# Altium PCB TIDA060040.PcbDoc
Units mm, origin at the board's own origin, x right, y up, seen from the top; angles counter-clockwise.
Board outline 50.79 x 50.79 mm, 2 copper layers (Top Layer, Bottom Layer), stack 1.575 mm thick; 49 components, 44 nets, 120 pads, 42 vias.
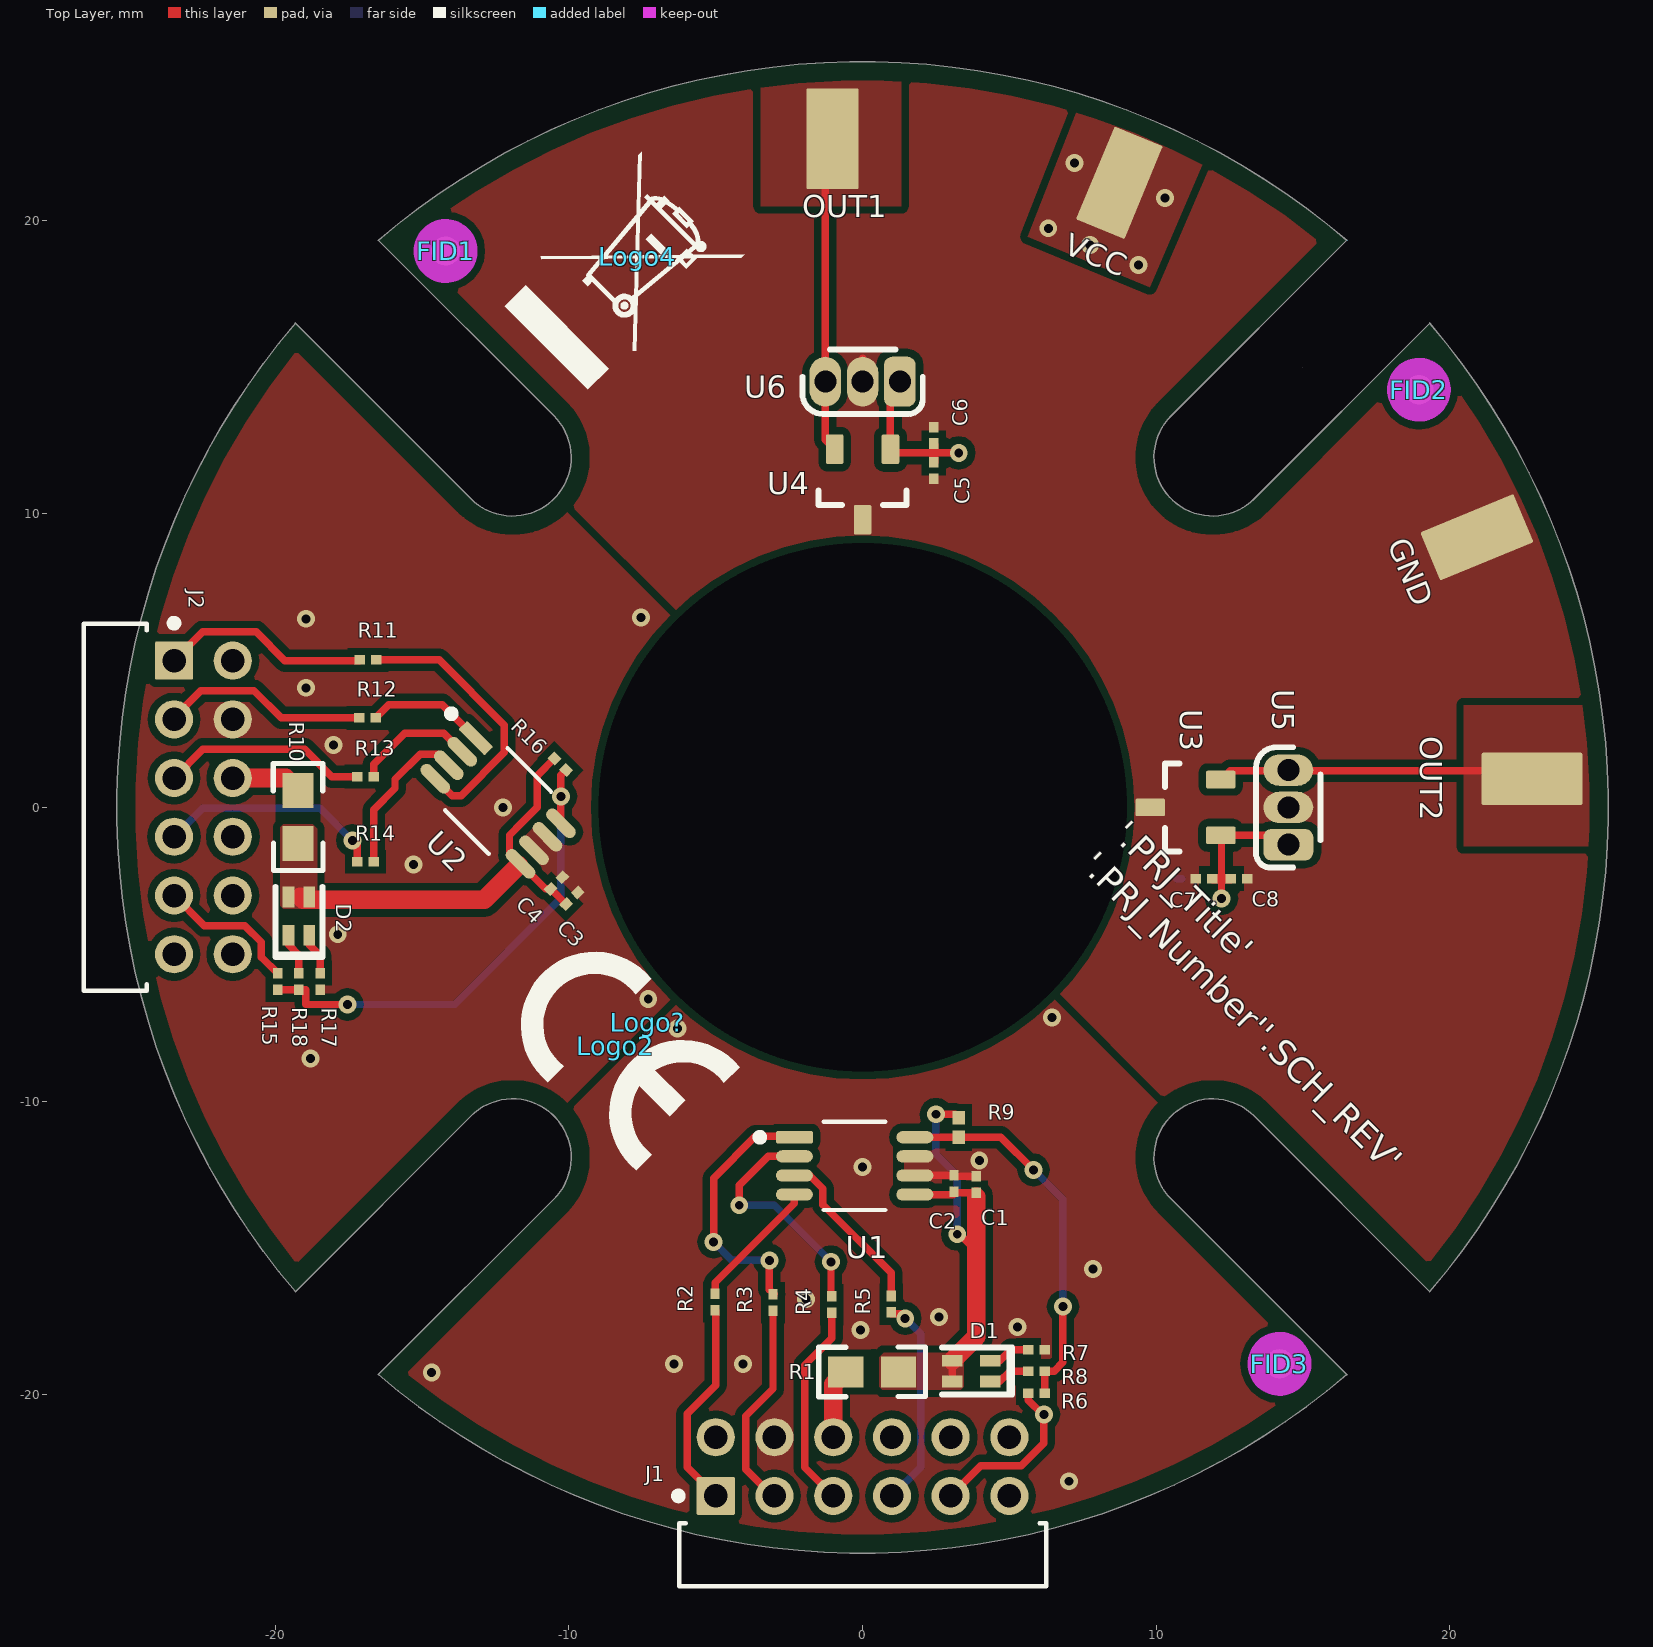
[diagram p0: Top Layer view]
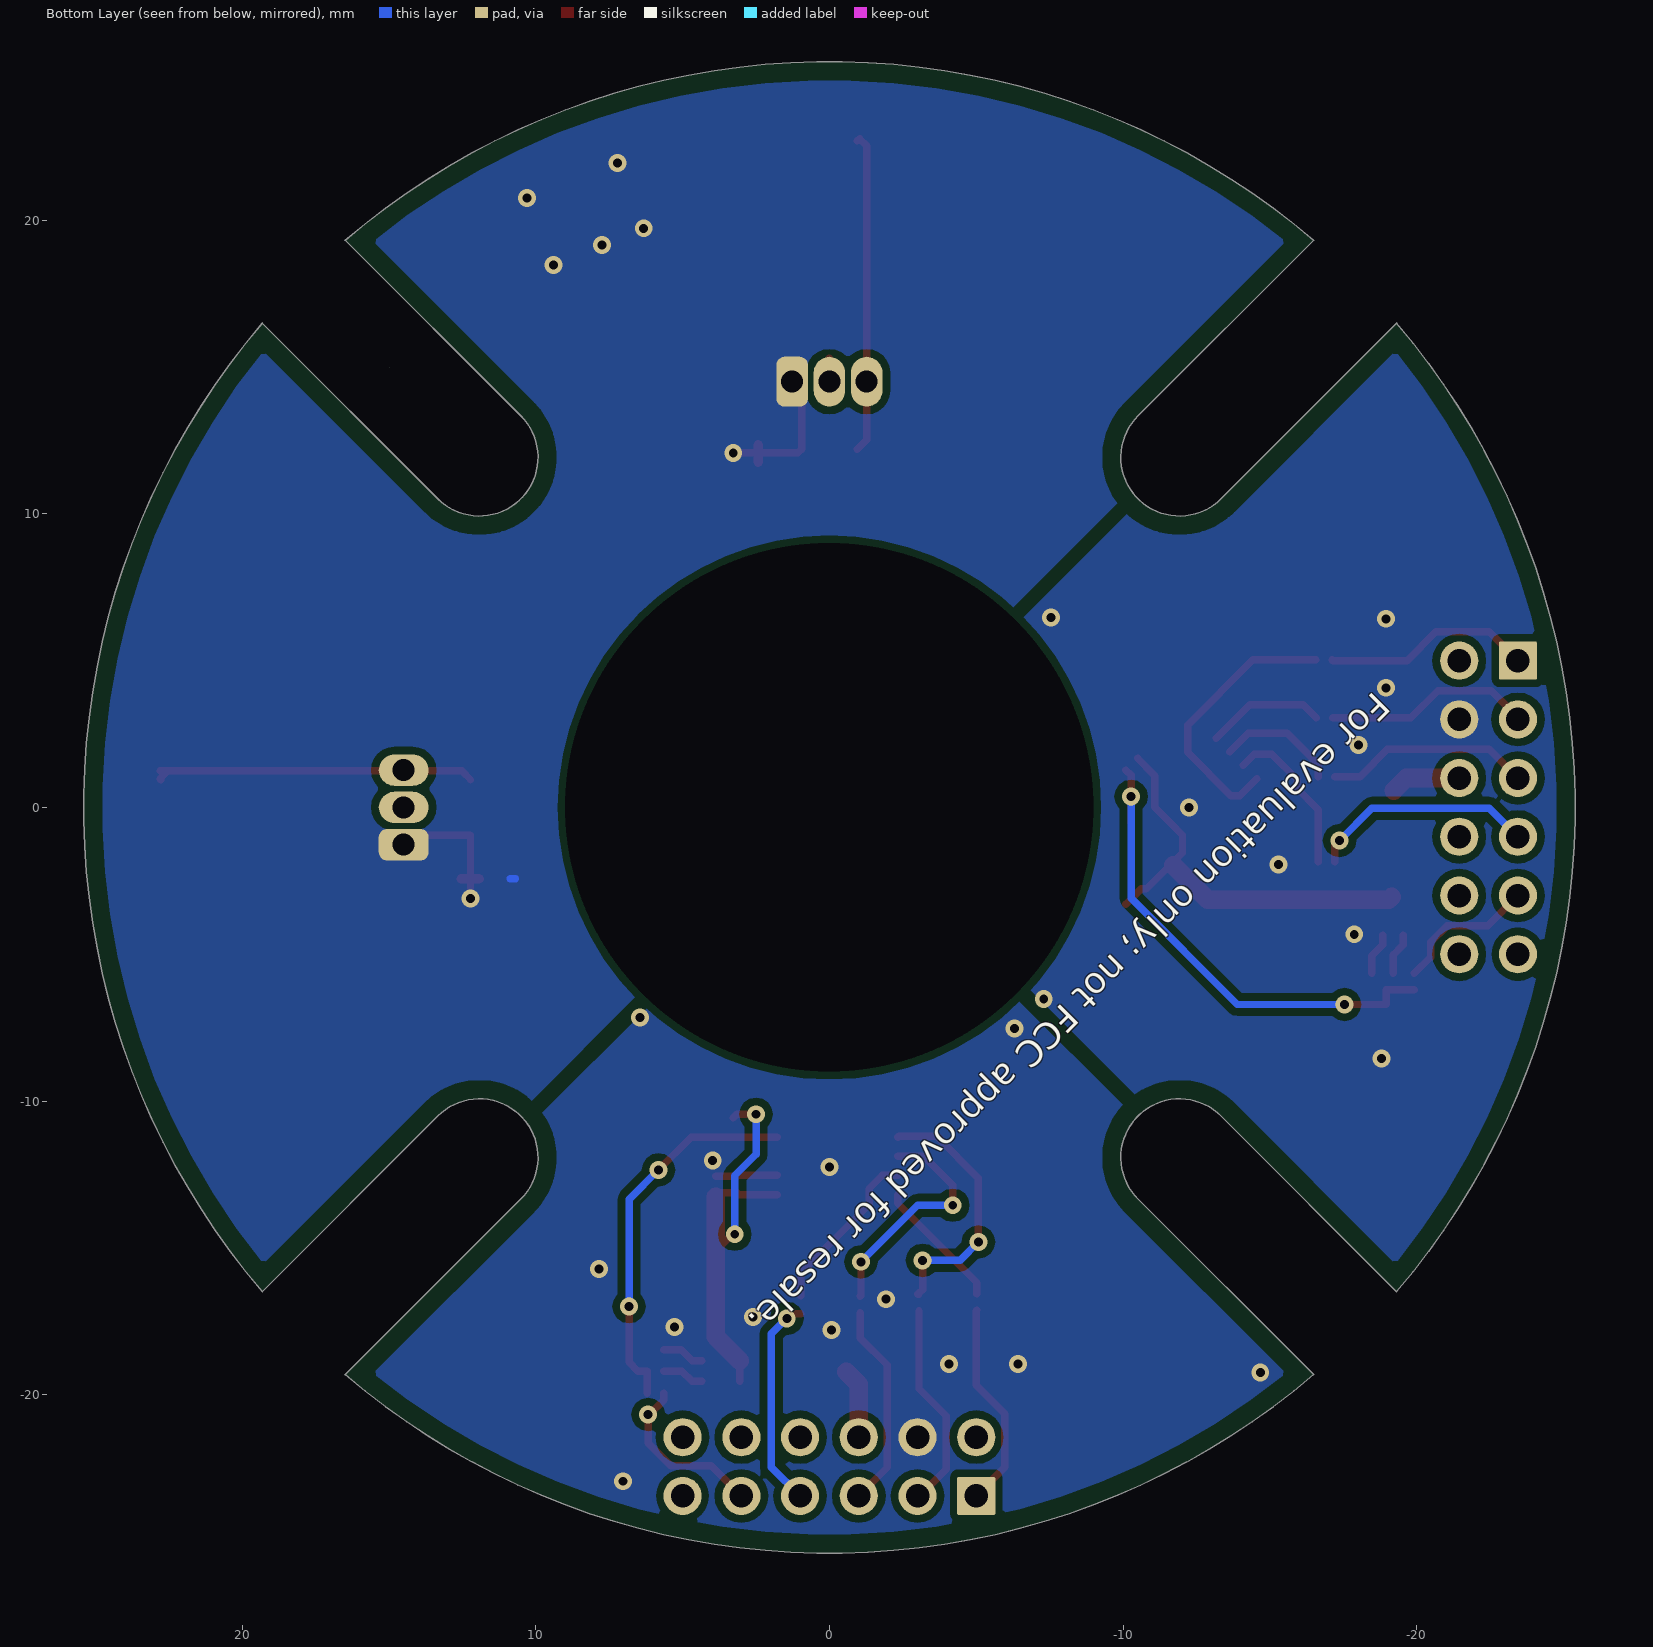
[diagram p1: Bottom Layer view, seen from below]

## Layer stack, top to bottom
Top Solder: solder mask 0.0102, Solder Resist, Dk 3.5
Top Layer: signal copper 0.0356
Dielectric1: core 1.5037, FR-4, Dk 4.8
Bottom Layer: signal copper 0.0356
Bottom Solder: solder mask 0.0102, Solder Resist, Dk 3.5

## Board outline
-19.325,-16.5 -13.339,-10.514 -13.339,-10.511 cw(c-11.925,-11.925) -10.511,-13.339 -10.514,-13.339 -16.5,-19.325 -16.493,-19.317 ccw(c0,0) 16.493,-19.317 16.5,-19.325 10.514,-13.339 10.511,-13.339 cw(c11.925,-11.925) 13.339,-10.511 13.339,-10.514 19.325,-16.5 19.317,-16.493 ccw(c0,0) 19.317,16.493 19.325,16.5 13.339,10.514 13.339,10.511 cw(c11.925,11.925) 10.511,13.339 10.514,13.339 16.5,19.325 16.493,19.317 ccw(c0,0) -16.493,19.317 -16.5,19.325 -10.514,13.339 -10.511,13.339 cw(c-11.925,11.925) -13.339,10.511 -13.339,10.514 -19.325,16.5 -19.317,16.493 ccw(c0,0)
cut-out: 16.5,19.325
cut-out: 15,15

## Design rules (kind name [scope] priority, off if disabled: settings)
AcuteAngle [All] p1: minimum=4.50000000000000E+0001 checktracksonly=FALSE
AssemblyTestPointUsage [All] p1: valid=2
BoardOutlineClearance BoardOutlineClearance_MountingHoles [OnCopper and InComponentClass('Mounting Holes')] p1: gap=1 ignorepadtopadclearanceinfootprint=FALSE
BoardOutlineClearance BoardOutlineClearance_Poly [OnCopper and IsPoly] p2: gap=0.635 ignorepadtopadclearanceinfootprint=FALSE
BoardOutlineClearance [OnCopper and Not InComponentClass('Logo') and not InComponentClass('FiducialMark') and not InRegion(1000,500,4000,800) and not InPoly] p3: gap=0.635 ignorepadtopadclearanceinfootprint=FALSE
Clearance Clearance_Keepouts [((IsTrack Or IsArc) And Not InPoly) And IsFree and IsKeepOut vs ((IsTrack Or IsArc) And Not InPoly) And IsFree and IsKeepOut] p1: gap=0 ignorepadtopadclearanceinfootprint=FALSE
Clearance Clearance_Poly [InPolygon] p2: gap=0.254 ignorepadtopadclearanceinfootprint=TRUE
Clearance Clearance_FiducialMark [IsKeepOut and InComponentClass('FiducialMark') vs IsPad and InComponentClass('FiducialMark')] p3: gap=0 ignorepadtopadclearanceinfootprint=FALSE
Clearance [All] p4: gap=0.2 ignorepadtopadclearanceinfootprint=TRUE
ComponentClearance ComponentClearance_MountingHoles_FiducialMarks [InComponentClass('Mounting Holes') vs InComponentClass('FiducialMark')] p1: gap=1.27 collisioncheckmode=3 verticalgap=0.254 showdistances=FALSE
ComponentClearance ComponentClearance_Shunt [InComponentClass('Header') vs InComponentClass('Shunt')] p2: gap=0 collisioncheckmode=3 verticalgap=0 showdistances=FALSE
ComponentClearance ComponentClearance_Logo [InComponentClass('Logo')] p3: gap=1.27 collisioncheckmode=3 verticalgap=0.254 showdistances=FALSE
ComponentClearance ComponentClearance_ScrewToNut [(HasFootprint('NY PMS 440 0025 PH')) vs (HasFootprint('Keystone_1902C'))] p4: gap=0.127 collisioncheckmode=3 verticalgap=0.254 showdistances=FALSE
ComponentClearance ComponentClearance_MountingHoles [InComponentClass('Mounting Holes')] p5: gap=6.35 collisioncheckmode=3 verticalgap=2540 showdistances=FALSE
ComponentClearance ComponentClearance_SmallPassives [HasFootprint('0201*') or HasFootprint('0402*') or HasFootprint('0508') or HasFootprint('0603*') or HasFootprint('0612') or HasFootprint('0805*') or HasFootprint('0815*') or HasFootprint('0830*') or HasFootprint('1206*') or HasFootprint('1210*') or HasFootprint('1808*') or HasFootprint('1812*') or HasFootprint('1825*') or HasFootprint('2010*') or HasFootprint('2220*') or HasFootprint('2225*') or HasFootprint('2512*') or HasFootprint('2728*') or HasFootprint('3518*') vs HasFootprint('0201*') or HasFootprint('0402*') or HasFootprint('0508') or HasFootprint('0603*') or HasFootprint('0612') or HasFootprint('0805*') or HasFootprint('0815*') or HasFootprint('0830*') or HasFootprint('1206*') or HasFootprint('1210*') or HasFootprint('1808*') or HasFootprint('1812*') or HasFootprint('1825*') or HasFootprint('2010*') or HasFootprint('2220*') or HasFootprint('2225*') or HasFootprint('2512*') or HasFootprint('2728*') or HasFootprint('3518*')] p6: gap=0.38 collisioncheckmode=3 verticalgap=0.254 showdistances=FALSE
ComponentClearance ComponentClearance_THtoSMT [IsThruComponent vs IsSMTComponent] p7: gap=1.016 collisioncheckmode=3 verticalgap=0.762 showdistances=FALSE
ComponentClearance ComponentClearance_THtoTH [IsThruComponent vs IsThruComponent] p8: gap=0.762 collisioncheckmode=3 verticalgap=0.762 showdistances=FALSE
ComponentClearance [All] p9: gap=0.762 collisioncheckmode=3 verticalgap=0.254 showdistances=FALSE
DiffPairsRouting [All] p1: maxlimit=2.54 minlimit=0.254 mostfreqgap=0.254 toplayer_minwidth=0.381 toplayer_maxwidth=0.381 toplayer_prefwidth=0.381 bottomlayer_minwidth=0.381 bottomlayer_maxwidth=0.381 bottomlayer_prefwidth=0.381 maxuncoupledlength=25.4
FabricationTestPointUsage TestPointUsage [All] p1: valid=2 allowmultiple=FALSE
FabricationTestpoint Testpoint [All] p1: side=3 testpointundercomponent=TRUE minsize=1.016 maxsize=2.54 preferedsize=1.524 minholesize=0 maxholesize=1.016 preferedholesize=0.813 testpointgrid=0.025 allowsidetop=TRUE allowsidebottom=TRUE usegrid=TRUE gridtolerance=0
FanoutControl Fanout_LCC [IsLCC] p1: bgadir=Out bgaviamode=Centered fanoutstyle=Auto fanoutdirection=Alternating viagrid=0.025 // Fanout_LCC (Default Rule)
FanoutControl Fanout_BGA [IsBGA] p2: bgadir=Out bgaviamode=Centered fanoutstyle=Auto fanoutdirection=Alternating viagrid=0.025 // Fanout_BGA (Default Rule)
FanoutControl Fanout_Default [All] p4: bgadir=Out bgaviamode=Centered fanoutstyle=Auto fanoutdirection=Alternating viagrid=0.025 // Fanout_Default (Default Rule)
FanoutControl Fanout_Small [(CompPinCount < 5)] p5: bgadir=Out bgaviamode=Centered fanoutstyle=Auto fanoutdirection=OutThenIn viagrid=0.025 // Fanout_Small (Default Rule)
HoleSize [All] p1: absolutevalues=TRUE maxlimit=25.4 minlimit=0.2 maxpercent=80.000 minpercent=20.000
MinimumAnnularRing MinimumAnnularRing_ThermalPadVias [IsVia and InAnyComponent] p1: minimumring=0.152
MinimumAnnularRing [All] p2: minimumring=0.152
MinimumSolderMaskSliver MinimumSolderMaskSliver_Logo [InComponentClass('Logo') vs InComponentClass('Logo')] p1: minsoldermaskwidth=0.018
MinimumSolderMaskSliver [All] p2: minsoldermaskwidth=0.1
PlaneConnect [All] p1: planeconnectstyle=Relief reliefexpansion=0.254 reliefentries=4 reliefconductorwidth=0.254 reliefairgap=0.254
PolygonConnect PolygonConnect_Trace [InNet('NetJ1_5') OR InNet('NetJ1_3')] p1: connectstyle=Direct reliefconductorwidth=0.254 reliefentries=4 polygonreliefangle="90 Angle" airgapwidth=0.254
PolygonConnect [All] p2: connectstyle=Direct reliefconductorwidth=0.254 reliefentries=4 polygonreliefangle="90 Angle" airgapwidth=0.254
RoutingVias ThermalPadVias [IsVia and InAnyComponent] p1: holewidth=0.2 width=0.5 viastyle="Through Hole" minholewidth=0.2 minwidth=0.5 maxholewidth=0.33 maxwidth=0.6
RoutingVias [All] p2: holewidth=0.254 width=0.559 viastyle="Through Hole" minholewidth=0.2 minwidth=0.5 maxholewidth=1.016 maxwidth=1.651
SilkToBoardRegionClearance [Not ((IsComment or IsDesignator) And (Hide <> 'False')) and not InRegion(1000,500,4000,800)] p1:
SilkToSilkClearance SilkToSilkClearance_Pb-FreeLogo [(HasFootprint('Pb-Free_Overlay_Medium') OR HasFootprint('Pb-Free_Overlay_Small')) vs (HasFootprint('Pb-Free_Overlay_Medium') OR HasFootprint('Pb-Free_Overlay_Small'))] p1: silktosilkclearance=0
SilkToSilkClearance [All] p2: silktosilkclearance=0.1
SilkToSolderMaskClearance SilkToComponentPadClearance [(IsPad or IsFill or IsRegion) and InAnycomponent] p1: minsilkscreentomaskgap=0.127 clearancetoexposedcopper=TRUE
SilkToSolderMaskClearance "Silk to Solder Mask Opening" [All] p2: minsilkscreentomaskgap=0.1 clearancetoexposedcopper=FALSE
SolderMaskExpansion [All] p1: expansion=0.05
UnRoutedNet [All] p1: checkbadconnections=TRUE
Width [All] p1: maxlimit=2.54 minlimit=0.152 preferedwidth=0.254 checkconnectedcopper=TRUE
14 further rules are at their usual default settings.

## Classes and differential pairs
component class Robotics: C1 C2 C3 C4 C5 C6 C7 C8 D1 D2 GND J1 J2 J4 J5 J? OUT1 OUT2 R1 R2 R3 R4 R5 R6 R7 R8 R9 R10 R11 R12 R13 R14 R15 R16 R17 R18 U1 U2 U3 U4 U5 U6 VCC
component class Robotics_HW: FID1 FID2 FID3 Logo2 Logo4 Logo? ZZ1 ZZ2 ZZ3
component class FiducialMark: FID1 FID2 FID3
component class AssemblyNote: ZZ1 ZZ2 ZZ3

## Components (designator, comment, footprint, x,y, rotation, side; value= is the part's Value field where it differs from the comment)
C1 "CL03A105MP3NSNC" 0201L 3.875,-12.845 r270 top value=1uF
C2 "GRM033R60J104KE19D" 0201_033L 3.115,-12.815 r90 top value=0.1uF
C3 "CL03A105MP3NSNC" 0201L -9.898,-3.098 r225 top value=1uF
C4 "GRM033R60J104KE19D" 0201_033L -10.425,-2.575 r45 top value=0.1uF
C5 "CL03A105MP3NSNC" 0201L 2.425,11.475 r90 top value=1uF
C6 "GRM033R60J104KE19D" 0201_033L 2.425,12.675 r90 top value=0.1uF
C7 "CL03A105MP3NSNC" 0201L 11.625,-2.425 r0 top value=1uF
C8 "GRM033R60J104KE19D" 0201_033L 12.824,-2.425 r0 top value=0.1uF
D1 "HSMF-C165" HSMF-C165_RG 3.7,-19.2 r0 top value=Rg
D2 "HSMF-C165" HSMF-C165_RG -19.2,-3.7 r270 top value=Rg
FID1 "Fiducial" Fiducial10-20 -14.2,18.95 r0 top
FID2 "Fiducial" Fiducial10-20 18.95,14.225 r0 top
FID3 "Fiducial" Fiducial10-20 14.2,-18.95 r0 top
GND "DRV5055 GND" Keystone_5017 20.925,9.2 r22.5 top
J1 "NRPN062PARN-RC" FP-NRPN062PARN-RC_HDR12-MFG 0,-25.45 r0 top
J2 "NRPN062PARN-RC" FP-NRPN062PARN-RC_HDR12-MFG -25.45,0 r270 top
Logo2 "CE Mark" CE_Mark_5mm -8.425,-8.125 r315 top
Logo4 "WEEE logo" WEEE_Minimum -7.675,18.75 r315 top
Logo? "FCC disclaimer" FCC_disclaimer -7.325,-7.325 r315 top
OUT1 "DRV5055 OUT2" Keystone_5017 -1.025,22.775 r90 top
OUT2 "DRV5055 OUT1" Keystone_5017 22.8,0.975 r180 top
R1 "CRCW06030000Z0EA" 0603M 0.325,-19.225 r180 top value=0
R2 "CRCW02010000Z0ED" 0201L -5.025,-16.845 r90 top value=0
R3 "CRCW02010000Z0ED" 0201L -3.05,-16.865 r90 top value=0
R4 "CRCW02010000Z0ED" 0201L -1.05,-16.935 r90 top value=0
R5 "CRCW02010000Z0ED" 0201L 0.975,-16.92 r90 top value=0
R6 "CRCW02010000Z0ED" 0201L 5.925,-19.95 r0 top value=0
R7 "RC0201JR-07150RL" 0201L 5.925,-18.475 r0 top value=150
R8 "RC0201JR-07150RL" 0201L 5.925,-19.2 r0 top value=150
R9 "RC0201JR-7D4K7L" 0201 3.275,-10.9 r90 top value=4.7k
R10 "CRCW06030000Z0EA" 0603M -19.225,-0.325 r90 top value=0
R11 "CRCW02010000Z0ED" 0201L -16.845,5.025 r0 top value=0
R12 "CRCW02010000Z0ED" 0201L -16.865,3.05 r0 top value=0
R13 "CRCW02010000Z0ED" 0201L -16.935,1.05 r0 top value=0
R14 "CRCW02010000Z0ED" 0201L -16.93,-1.85 r0 top value=0
R15 "CRCW02010000Z0ED" 0201L -19.925,-5.925 r270 top value=0
R16 "CRCW02010000Z0ED" 0201L -10.296,1.471 r135 top value=4.7k
R17 "RC0201JR-07150RL" 0201L -18.475,-5.925 r270 top value=150
R18 "RC0201JR-07150RL" 0201L -19.2,-5.925 r270 top value=150
U1 "PTMAG5170A1EDGKQ1" DGK0008A-IPC_C -0.27,-12.21 r0 top
U2 "PTMAG5170A1EDGKQ1" DGK0008A-IPC_C -12.413,0.219 r315 top locked
U3 "DRV5055A1QDBZT" DBZ0003A_N 11,0 r180 top
U4 "DRV5055A1QDBZT" DBZ0003A_N 0,11 r270 top
U5 "DRV5055A1QLPGM" LPG0003A 14.5,0 r90 top
U6 "DRV5055A1QLPGM" LPG0003A 0,14.5 r180 top
VCC "DRV5055 VCC" Keystone_5017 8.75,21.275 r247.5 top
ZZ1 "These assemblies are ESD sensitive, ESD precautions shall be observed." AssemblyNote -61.119,49.567 r0 top
ZZ2 "These assemblies must be clean and free from flux and all contaminants. Use of no clean flux is not acceptable." AssemblyNote -61.119,47.318 r0 top
ZZ3 "These assemblies must comply with workmanship standards IPC-A-610 Class 2, unless otherwise specified." AssemblyNote -61.119,45.068 r0 top

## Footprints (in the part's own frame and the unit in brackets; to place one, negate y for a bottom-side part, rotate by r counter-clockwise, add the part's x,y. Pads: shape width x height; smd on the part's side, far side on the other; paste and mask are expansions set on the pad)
0201 [mm] "Data from Kemet datasheet CC101_COM dated 7/28/11"
  rect 0.46x0.42 smd mask+0.048: 1(-0.33,0) 2(0.33,0)
  body extent -0.31,-0.16 0.31,0.16, height 0.26
0201_033L [mm] "0201"
  rect 0.36x0.32 smd mask+0.048: 1(-0.28,0) 2(0.28,0)
  body extent -0.31,-0.16 0.31,0.16, height 0.33
0201L [mm] "Data from Kemet datasheet CC101_COM dated 7/28/11"
  rect 0.36x0.32 smd mask+0.048: 1(-0.28,0) 2(0.28,0)
  body extent -0.31,-0.16 0.31,0.16, height 0.26
0603M [mm] "0603 from SM-752 data"
  rect 1.2x1.05 smd: 1(-0.9,0) 2(0.9,0)
  silkscreen extent -1.82,-0.84 1.82,0.84, body extent -0.87,-0.47 0.87,0.47, height 1
AssemblyNote [mm] "Assembly Note"
CE_Mark_5mm [mm] "Minimum text height for CE Mark"
  silkscreen extent -3.5,-2.5 3.5,2.5
DBZ0003A_N [mm] "SOT23, 3-Leads, Body 2.9x1.3mm, Pitch 0.95mm, Lead Span 2.4mm, IPC Medium Density"
  rrect17% 1x0.6 smd: 1(-1.2,0.95) 2(-1.2,-0.95) 3(1.2,0)
  silkscreen extent 0.2,-1.5 0.7,1.5, body extent -1.26,-1.46 1.26,1.46, height 0.98
DGK0008A-IPC_C [mm]
  rrect24% 1.257x0.418 smd paste+0 mask+0: 1(-2.051,0.975)
  rrect100% 1.257x0.418 smd paste+0 mask+0: 2(-2.051,0.325) 3(-2.051,-0.325) 4(-2.051,-0.975) 5(2.051,-0.975) 6(2.051,-0.325) 7(2.051,0.325) 8(2.051,0.975)
  silkscreen extent -3.35,-1.5 1.05,1.5, body extent -2.78,-1.6 2.78,1.6, height 0.25
FCC_disclaimer [mm]
Fiducial10-20 [mm]
  round 1 smd mask+0.5: 1(0,0)
  Top Layer keep-out circle w1.178: c0,0 r0.5
FP-NRPN062PARN-RC_HDR12-MFG [mm]
  rrect8% 1.3x1.3 hole 0.8 paste-1000 mask+0: 1(-5,2)
  round 1.3 hole 0.8 paste-1000 mask+0: 2(-5,4) 3(-3,2) 4(-3,4) 5(-1,2) 6(-1,4) 7(1,2) 8(1,4) 9(3,2) 10(3,4) 11(5,2) 12(5,4)
  silkscreen extent -6.4,-1.07 6.25,2.12, body extent -6.35,-5.02 6.35,4.75, height 0.25
HSMF-C165_RG [mm] "SMD, 4-Leads, Body 1.6x0.8mm"
  rect 0.7x0.4 smd: 1(-0.65,0.35) 2(-0.65,-0.35) 3(0.65,0.35) 4(0.65,-0.35)
  silkscreen extent -1,-0.8 1.5,0.8, body extent -0.85,-0.45 0.85,0.45, height 0.51
Keystone_5017 [mm] "PC Test Point, SMT"
  rrect6% 3.43x1.78 smd: 1(0,0)
  body extent -1.35,-0.51 1.35,0.51, height 1.51
LPG0003A [mm] "TO, Flat Index; 3 In-Line, Axial Leads Texas Instruments Recommended"
  rrect50% 1.07x1.7 hole 0.75: 1(-1.27,0)
  oval 1.07x1.7 hole 0.75: 2(0,0) 3(1.27,0)
  silkscreen extent -2.05,-1.1 2.05,1.1, body extent -2,-0.98 2,0.54, height 5.06
WEEE_Minimum [mm] "WEEElie bin"
  silkscreen extent -2.42,-4.37 2.52,2.65

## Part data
C1 C3 C5 C7: library part CMP-0009656-3, "CAP, CERM, 1 uF, 10 V, +/- 20%, X5R, 0201", Cap_Case=0201, Manufacturer="Samsung Electro-Mechanics", TempCo=X5R, Tolerance_%=20%, Value1=Unknown, Value2=10V, ValueDisplayed=1uF
C2 C4 C6 C8: library part CMP-0009690-3, "CAP, CERM, 0.1 uF, 6.3 V, +/- 10%, X5R, 0201", Cap_Case=0201, Manufacturer=MuRata, Supplier Part Number 1=490-3167-1-ND, TempCo=X5R, Tolerance_%=10%, Value1=Unknown, Value2=6.3V, ValueDisplayed=0.1uF
D1 D2: library part CMP-0002934-2, "LED, Rg, SMD", Color=RG, Manufacturer=Avago, Supplier Part Number 1=516-1419-1-ND, Value1=W, Value2=2.2V
FID1 FID2 FID3: library part CMP-0077181-1, "Fiducial mark.  There is nothing to buy or mount.", Manufacturer=N/A
GND OUT1 OUT2 VCC: library part CMP-0078225-1, "PC Test Point, SMT", Manufacturer=Keystone, PartNumber=5017, Supplier Part Number 1=36-5017CT-ND
J1 J2: library part CMP-0090321-1, Current_A=2A, Digikey Part Number=S5803-06-ND, Manufacturer="Sullins Connector Solutions", Operating Temperature Range="-40°C to +105°C", Voltage_V=150V
Logo2: library part CMP-0074844-1
Logo4: library part CMP-0074769-1
Logo?: library part CMP-0074847-1, "FCC_disclaimer"
R1 R10: library part CMP-0025697-4, "RES, 0, 5%, 0.1 W, AEC-Q200 Grade 0, 0603", Manufacturer=Vishay-Dale, Power_W=100mW, Supplier Part Number 1=541-0.0GCT-ND, TempCo="200 ppm/C", Tolerance_%=5%, Value2=0.1W, Value_Code=0000, ValueDisplayed=0
R2 R3 R4 R5 R6 R11 R12 R13 R14 R15: library part CMP-0027008-4, "RES, 0, 5%, 0.05 W, 0201", Manufacturer=Vishay-Dale, Power_W=50mW, Supplier Part Number 1=72M6743, TempCo=ppm/C, Tolerance_%=5%, Value2=0.05W, Value_Code=0000, ValueDisplayed=0
R7 R8 R17 R18: library part CMP-0027035-1, "RES, 150, 5%, 0.05 W, 0201", Manufacturer="Yageo America", Power_W=50mW, Supplier Part Number 1=311-150NCT-ND, TempCo="200 ppm/C", Tolerance_%=5%, Value2=0.05W, Value_Code=150R, ValueDisplayed=150
R9: library part CMP-0027242-1, "RES, 4.7 k, 5%, 0.05 W, 0201", Manufacturer="Yageo America", Power_W=50mW, Supplier Part Number 1=603-RC0201JR-7D4K7L, TempCo="200 ppm/C", Tolerance_%=5%, Value2=0.05W, Value_Code=4k70, ValueDisplayed=4.7k
R16: library part CMP-0027242-1, "RES, 4.7 k, 5%, 0.05 W, 0201", Alternate PartNumber=ERA-1AEB472C, Manufacturer="Yageo America", PartNumber=RC0201JR-7D4K7L, Power_W=50mW, Supplier Part Number 1=603-RC0201JR-7D4K7L, TempCo="200 ppm/C", Tolerance_%=5%, Value2=0.05W, Value_Code=4k70, ValueDisplayed=4.7k
U1 U2: library part CMP-0091328-1, "Automotive, 3D high-precision linear Hall effect sensor with SPI bus interface 8-VSSOP -40 to 150", Manufacturer="Texas Instruments", Max Supply Voltage=5.5V, Min Supply Voltage=2.3V, Operating Supply Current=3.4mA, Operating Temperature Range="-40°C to +150°C"
U3 U4: library part CMP-0081694-1, "High Accuracy 3.3 V or 5 V Ratiometric Bipolar Hall Effect Sensor Family, DBZ0003A (SOT-23-3)", Alternate Manufacturer="Texas Instruments", Alternate PartNumber=DRV5055A1QDBZR, Operating Temprature Range="-40 to 125 C", Rating=Catalog
U5 U6: library part CMP-0081697-1, "High Accuracy 3.3 V or 5 V Ratiometric Bipolar Hall Effect Sensor Family, LPG0003A (TO-92-3)", Alternate Manufacturer="Texas Instruments", Alternate PartNumber=DRV5055A1QLPG, Operating Temprature Range="-40 to 125 C", Rating=Catalog
ZZ1: library part CMP-0077236-1
ZZ2: library part CMP-0077237-1
ZZ3: library part CMP-0077238-1

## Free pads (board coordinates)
  round 0 hole 18 unplated mask+0: 1(0,0)

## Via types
v1: diameter 0.61, hole 0.305, Top Layer to Bottom Layer, tented both sides, 42 vias

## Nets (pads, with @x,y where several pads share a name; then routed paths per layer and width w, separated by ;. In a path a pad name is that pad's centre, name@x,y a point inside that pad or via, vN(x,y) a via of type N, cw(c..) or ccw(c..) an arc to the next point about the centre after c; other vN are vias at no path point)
5V_1: J2.2
5V_2: J1.2
\ALERT_1: R15.2 R16.1 R18.2 U2.8 | length 17
  Top Layer w0.254: R15.2 R18.2 -18.962,-6.205 -18.962,-6.712 v1(-17.544,-6.712) ; U2.8 v1(-10.273,0.375) -10.273,1.098 R16.1
  Bottom Layer w0.254: v1(-17.544,-6.712) -13.887,-6.712 -10.273,-3.098 v1(-10.273,0.375)
\ALERT_2: R6.2 R8.2 R9.1 U1.8 | length 13
  Top Layer w0.254: U1.8 4.71,-11.235 v1(5.822,-12.347) ; R6.2 R8.2 6.525,-19.2 6.825,-18.9 v1(6.825,-17)
  Bottom Layer w0.254: v1(5.822,-12.347) 6.825,-13.35 v1(6.825,-17)
\CS_1: R11.2 U2.4 | length 9.4
  Top Layer w0.254: R11.2 -14.425,5.025 -12.2,2.8 -12.2,1.875 -13.675,0.4 -13.972,0.4 U2.4
\CS_2: R2.2 U1.4 | length 4.5
  Top Layer w0.254: R2.2 -5.025,-16.194 -2.321,-13.489 U1.4
GND_1: C3.1 C4.2 J2.4 R17.2 U2.6 U2.7
  other v1: -18.8,-8.55 -7.3,-6.525 -17.875,-4.321 -15.3,-1.95 -12.25,0 -18.025,2.125 -18.95,4.075 -18.95,6.425 -7.55,6.475
GND_2: C1.1 C2.2 J1.4 R7.2 U1.6 U1.7 | length 2.1
  Top Layer w0.254: U1.6 C2.2 3.15,-12.57 3.155,-12.565 C1.1
  other v1: 7.025,-22.95 -14.675,-19.25 -6.425,-18.95 -4.075,-18.95 -0.075,-17.804 5.275,-17.7 2.6,-17.35 -1.925,-16.75 7.85,-15.725 0,-12.25 3.975,-12.025 -6.3,-7.525 6.45,-7.15
GND_3: C5.1 C6.2 C7.1 C8.2 GND.1 U3.3 U4.3 U5.2 U6.2 | length 0.8
  Top Layer w0.254: U6.2 U6.2@0,15.3
MISO_1: R14.2 U2.3 | length 5.4
  Top Layer w0.254: R14.2 -16.65,-0.075 -15.925,0.65 -15.925,0.958 -15.071,1.812 -14.465,1.812 U2.3
MISO_2: R5.2 U1.3 | length 5.8
  Top Layer w0.254: U1.3 -1.793,-12.535 -1.35,-12.978 -1.35,-13.525 0.975,-15.85 R5.2
MOSI_1: R13.2 U2.2 | length 4.1
  Top Layer w0.254: R13.2 -16.655,1.47 -15.6,2.525 -14.259,2.525 U2.2
MOSI_2: R4.2 U1.2 | length 8.1
  Top Layer w0.254: v1(-4.2,-13.55) -4.2,-12.87 -3.215,-11.885 U1.2 ; v1(-1.075,-15.475) -1.075,-16.63 R4.2
  Bottom Layer w0.254: v1(-4.2,-13.55) -3,-13.55 v1(-1.075,-15.475)
NetD1_3: D1.3 R7.1 | length 1.5
  Top Layer w0.254: D1.3 4.675,-18.85 5.05,-18.475 R7.1
NetD1_4: D1.4 R8.1 | length 1.4
  Top Layer w0.254: D1.4 4.675,-19.55 5.025,-19.2 R8.1
NetD2_3: D2.3 R17.1 | length 1.5
  Top Layer w0.254: D2.3 -18.85,-4.675 -18.475,-5.05 R17.1
NetD2_4: D2.4 R18.1 | length 1.4
  Top Layer w0.254: D2.4 -19.55,-4.675 -19.2,-5.025 R18.1
NetJ1_1: J1.1 R2.1 | length 7.1
  Top Layer w0.254: R2.1 -5,-17.15 -5,-19.675 -5.977,-20.652 -5.977,-22.473 J1.1
NetJ1_3: J1.3 R3.1 | length 7.7
  Top Layer w0.254: R3.1 -3.05,-19.8 -3.977,-20.727 -3.977,-22.548 -3,-23.525 J1.3 J1.3@-3,-23.025
NetJ1_5: J1.5 R4.1 | length 7
  Top Layer w0.254: R4.1 -1.05,-18.075 -1.977,-19.002 -1.977,-22.473 J1.5
NetJ1_6: J1.6 R1.2 | length 2.4
  Top Layer w0.635: J1.6 -1,-19.65 R1.2
NetJ1_7: J1.7 R5.1 | length 7.2
  Top Layer w0.254: R5.1@0.975,-17.25 1.301,-17.25 v1(1.452,-17.401)
  Bottom Layer w0.254: J1.7 1.975,-22.475 1.975,-21.859 1.977,-21.857 1.977,-17.926 v1(1.452,-17.401)
NetJ1_9: J1.9 R6.1 | length 5.9
  Top Layer w0.254: J1.9 4.023,-22.427 5.405,-22.427 6.175,-21.657 v1(6.175,-20.675) 6.128,-20.675 5.645,-20.192 R6.1
NetJ2_1: J2.1 R11.1 | length 7.1
  Top Layer w0.254: J2.1 -22.473,5.977 -20.652,5.977 -19.675,5 -17.15,5 R11.1
NetJ2_3: J2.3 R12.1 | length 7.7
  Top Layer w0.254: J2.3@-23.025,3 J2.3 -23.525,3 -22.548,3.977 -20.727,3.977 -19.8,3.05 R12.1
NetJ2_5: J2.5 R13.1 | length 7
  Top Layer w0.254: J2.5 -22.473,1.977 -19.002,1.977 -18.075,1.05 R13.1
NetJ2_6: J2.6 R10.2 | length 2.4
  Top Layer w0.635: J2.6 -19.65,1 R10.2
NetJ2_7: J2.7 R14.1 | length 7.7
  Top Layer w0.254: v1(-17.375,-1.125) -17.21,-1.29 R14.1
  Bottom Layer w0.254: J2.7 -22.473,-0.023 -18.477,-0.023 v1(-17.375,-1.125)
NetJ2_9: J2.9 R15.1 | length 4.9
  Top Layer w0.254: J2.9 -22.427,-4.023 -21.045,-4.023 -20.473,-4.595 -20.473,-5.097 R15.1
NetOUT1_1: OUT1.1 U4.2 U6.3 | length 10.2
  Top Layer w0.254: U6.3 -1.27,12.52 U4.2 ; U6.3@-1.27,15.25 -1.27,22.53 OUT1.1 OUT1.1@-0.95,22.7
NetOUT2_1: OUT2.1 U3.2 U5.3 | length 10.4
  Top Layer w0.254: U3.2@12.225,0.95 12.52,1.245 U5.3@14.525,1.245 ; U5.3@15.25,1.245 OUT2.1@22.53,1.245 ; OUT2.1@22.775,0.95 OUT2.1 OUT2.1@22.53,1.245 ; OUT2.1@22.8,1.245 OUT2.1@22.53,1.245
PD2_1: J2.8
PD2_2: J1.8
PN4_1: J2.12
PN4_2: J1.12
PN5_1: J2.10
PN5_2: J1.10
PP1_1: J2.11
PP1_2: J1.11
SCLK_1: R12.2 U2.1 | length 4.1
  Top Layer w0.254: R12.2 -16.135,3.5 -14.315,3.5 U2.1
SCLK_2: R3.2 U1.1 | length 9
  Top Layer w0.254: v1(-5.075,-14.8) -5.075,-12.625 -3.65,-11.2 -2.356,-11.2 U1.1 ; v1(-3.175,-15.425) -3.175,-16.42 -3.01,-16.585 R3.2
  Bottom Layer w0.254: v1(-5.075,-14.8) -4.45,-15.425 v1(-3.175,-15.425) v1@-3.175,-15.345
VCC_1: C3.2 C4.1 D2.1 D2.2 R10.1 R16.2 U2.5 | length 14.5
  Top Layer w0.254: R16.2 -11.079,1.084 -11.079,0.004 -11.618,-0.536 -12.025,-0.942 -12.025,-1.548 U2.5 -10.799,-2.773 C4.1 C3.2@-10.1,-3.296
  Top Layer w0.635: -19.15,-3.05 -19.05,-3.15 -12.881,-3.15 U2.5@-11.706,-1.975
VCC_2: C1.2 C2.1 D1.1 D1.2 R1.1 R9.2 U1.5 | length 15
  Top Layer w0.254: U1.5 3.095,-13.185 3.15,-13.13 3.87,-13.13 C1.2 ; v1(2.5,-10.45) 3.155,-10.45 R9.2 ; D1.2 D1.1 ; v1(3.225,-14.538) 3.225,-14.45 3.875,-15.1
  Top Layer w0.635: D1.1 3.875,-18.025 3.875,-15.1 C1.2@3.875,-13.263
  Bottom Layer w0.254: v1(2.5,-10.45) 2.5,-11.813 3.225,-12.538 v1(3.225,-14.538)
VCC_3: C5.2 C6.1 C7.2 C8.1 U3.1 U4.1 U5.1 U6.1 VCC.1 | length 10.8
  Top Layer w0.254: U6.1 0.95,14.18 U4.1 1.075,12.075 2.425,12.075 v1(3.275,12.075) ; v1(12.225,-3.1) 12.225,-2.425 12.225,-0.95 14.18,-0.95 U5.1@14.525,-1.295
  Top Layer w0.318: C5.2 2.425,12.075 C6.1@2.425,12.35 ; C7.2@11.925,-2.425 12.225,-2.425 C8.1
  Bottom Layer w0.254: 10.7,-2.425 10.865,-2.425
  other v1: 9.4,18.475 7.75,19.15 6.325,19.725 10.3,20.75 7.221,21.95
pads on no net: FID1.1 FID2.1 FID3.1

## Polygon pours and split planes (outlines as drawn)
VCC_3 on Top Layer "Top Layer-VCC_3" (solid, pour order 78): 7.556,24.388 5.619,19.436 9.773,17.713 11.887,22.612
NetOUT2_1 on Top Layer "Top Layer-NetTP2_1" (solid, pour order 92): 25.225,3.05 24.8,3.475 20.475,3.475 20.475,-1.325 24.8,-1.325 25.225,-0.9
NetOUT1_1 on Top Layer "Top Layer-NetTP3_1" (solid, pour order 86): -3.05,25.225 -3.475,24.8 -3.475,20.475 1.325,20.475 1.325,24.8 0.9,25.225
GND_2 on Top Layer "GND_2_TOP" (solid, pour order 104): -17.912,-17.913 -10.425,-25.4 10.8,-25.4 18.1,-18.1 4.602,-4.602 -4.602,-4.602
no net on Top Layer "Top Layer-No Net 1" (solid, pour order 128): 1.6,-11.675
no net on Top Layer "Top Layer-No Net 3" (solid, pour order 126): -21.45,-1
VCC_1 on Top Layer "VCC_1_TOP" (solid, pour order 96): -18.575,-0.725 -18.725,-0.575 -19.725,-0.575 -19.825,-0.675 -19.825,-3.35 -19.725,-3.45 -18.675,-3.45 -18.575,-3.35
GND_1 on Top Layer "GND_1_TOP" (solid, pour order 98): -17.913,17.912 -25.4,10.425 -25.4,-10.8 -18.1,-18.1 -4.602,-4.602 -4.602,4.602
GND_3 on Top Layer "GND_3_TOP" (solid, pour order 120): 18.044,-18.044 36.038,-0.051 -0.044,36.031 -18.038,18.038
no net on Top Layer "Top Layer-No Net" (solid, pour order 76): -4.925,-60.225
VCC_2 on Top Layer "VCC_2_TOP1" (solid, pour order 102): 0.725,-18.575 0.575,-18.725 0.575,-19.725 0.675,-19.825 3.35,-19.825 3.45,-19.725 3.45,-18.675 3.35,-18.575
no net on Top Layer "Top Layer-No Net 3" (solid, pour order 84): 1,-21.45
no net on Top Layer "Top Layer-No Net 5" (solid, pour order 71): 0.05,-11.625
no net on Top Layer "TOP_LAYER_NONET_P073" (solid, pour order 73): -30.41,-8.323
no net on Top Layer "TOP_LAYER_NONET_P075" (solid, pour order 75): -3.606,-11.881
VCC_2 on Top Layer "TOP_LAYER_VCC_2_P074" (solid, remove dead copper, pour order 74): -32.214,-2.074
VCC_2 on Top Layer "TOP_LAYER_VCC_2_P072" (solid, remove dead copper, pour order 72): -32.722,-2.709
no net on Top Layer "TOP_LAYER_NONET_P077" (solid, remove dead copper, pour order 77): -35.516,1.101
VCC_3 on Bottom Layer "VCC_3_BOTTOM" (solid, pour order 118): 18.038,18.088 10.675,25.45 -10.55,25.45 -17.725,18.275 -4.102,4.652 4.602,4.652
VCC_3 on Bottom Layer "VCC_3_BOTTOM" (solid, pour order 116): 18.2,-18.05 25.5,-10.75 25.5,10.475 17.925,18.05 4.702,4.827 4.702,-4.552
GND_2 on Bottom Layer "GND_2_BOTTOM" (solid, pour order 114): -18.025,-18.175 -10.725,-25.475 10.5,-25.475 17.675,-18.3 4.052,-4.677 -4.527,-4.677
GND_1 on Bottom Layer "GND_1_BOTTOM" (solid, pour order 100): -18.175,18.025 -25.475,10.725 -25.475,-10.5 -18.3,-17.675 -4.677,-4.052 -4.677,4.527

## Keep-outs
Keep-Out Layer:
  text ".Layer_Name" at -51.162,-69.498 h1.52

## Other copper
Top Layer:
  pour cut-out: 1.425,-13.351 1.025,-12.951 1.025,-11.499 1.425,-11.099
  text ".Layer_Name" at -51.162,-69.498 h1.52
Bottom Layer:
  text ".Layer_Name" at -51.162,-69.498 h1.52

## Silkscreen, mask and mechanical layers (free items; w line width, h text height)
Top Overlay:
  text "'.PRJ_Title'  / '.PRJ_Number''.SCH_REV'" at 7.2,-2.25 h1.5 r315
  text ".Layer_Name" at -51.162,-69.498 h1.52
Bottom Overlay:
  text ".Layer_Name" at -51.162,-69.498 h1.52
Top Paste:
  text ".Layer_Name" at -51.162,-69.498 h1.52
Bottom Paste:
  text ".Layer_Name" at -51.162,-69.498 h1.52
Top Solder:
  text ".Layer_Name" at -51.162,-69.498 h1.52
  text ".Layer_Name" at -51.162,-69.498 h1.52
Bottom Solder:
  text ".Layer_Name" at -51.162,-69.498 h1.52
Drill Guide:
  text ".Layer_Name" at -51.162,-69.498 h1.52
M1 Board Outline:
  circle w0.1: c0,0 r7.5
  lines w0.025: -19.325,-16.5 -13.339,-10.514 ; -19.325,16.5 -13.339,10.514 ; -19.317,-16.493 cw(c0,0) -19.317,16.493 ; -16.5,-19.325 -10.514,-13.339 ; -16.5,19.325 -10.514,13.339 ; -16.493,-19.317 ccw(c0,0) 16.493,-19.317 ; -16.493,19.317 cw(c0,0) 16.493,19.317 ; -13.339,-10.511 cw(c-11.925,-11.925) -10.511,-13.339 ; -13.339,10.511 ccw(c-11.925,11.925) -10.511,13.339 ; 10.511,-13.339 cw(c11.925,-11.925) 13.339,-10.511 ; 10.514,-13.339 16.5,-19.325 ; 13.339,-10.514 19.325,-16.5 ; 16.5,19.325 10.514,13.339 10.511,13.339 ccw(c11.925,11.925) 13.339,10.511 13.339,10.514 19.325,16.5 ; 19.317,-16.493 ccw(c0,0) 19.317,16.493
  text ".Layer_Name" at -51.162,-69.498 h1.52
M2 Board Dimensions:
  rectangle: -65.818,-54.678 -62.643,-51.503
  rectangle: -62.643,-57.853 -53.118,-54.678
  lines w0.178: -65.818,-54.678 -40.418,-54.678 ; -62.643,-57.853 -62.643,-51.503 ; -59.468,-57.853 -59.468,-51.503 ; -53.118,-57.853 -53.118,-51.503 ; -46.768,-57.853 -46.768,-51.503 ; -65.818,-57.853 -40.418,-57.853 -40.418,-51.503 -65.818,-51.503 -65.818,-57.853
  text ".Layer_Name" at -51.162,-69.498 h1.52
M3 3D STEP Top:
  text ".Layer_Name" at -51.162,-69.498 h1.52
M4 3D STEP Bottom:
  text ".Layer_Name" at -51.162,-69.498 h1.52
M5 Assembly Top:
  lines w0.254: -73.235,-71.319 94.405,-71.319 ; -73.235,-66.154 94.456,-66.154 ; -73.235,-60.989 -73.235,-76.483 28.492,-76.483 94.456,-76.483 94.456,-60.99 -73.222,-60.99 -73.222,-76.483 -33.204,-76.483 ; -10.624,-76.483 -10.624,-60.99 ; 21.558,-66.154 21.558,-60.99 ; 42.894,-66.154 42.894,-60.99 ; 58.693,-76.649 58.693,-71.497
  text "COMPONENTS MARKED 'DNP' SHOULD NOT BE POPULATED." at -36.519,-55.782 h1.52
  text "ASSEMBLY VARIANT:" at -36.532,-58.716 h1.52
  text ".VariantName" at -10.217,-58.716 h1.52
  text "PCB VIEWED FROM TOP SIDE" at -71.622,-64.347 h1.52
  text "BOARD #:" at -8.719,-64.347 h1.52
  text ".PRJ_Number" at 5.137,-64.347 h1.52
  text "REV:" at 26.587,-64.347 h1.52
  text ".PCB_Rev" at 33.991,-64.347 h1.52
  text "SVN REV:" at 47.872,-64.347 h1.52
  text ".VersionControl_RevNumber" at 60.725,-64.347 h1.52
  text "TID #:" at -8.719,-69.511 h1.52
  text ".TID" at 5.137,-69.511 h1.52
  text "PLOT NAME =" at -71.622,-74.727 h1.52
  text ".plot_File_Name" at -51.162,-74.727 h1.52
  text "GENERATED    :" at -8.668,-74.727 h1.52
  text ".Print_Date" at 13.417,-74.727 h1.52
  text ".Print_Time" at 31.934,-74.727 h1.52
  text "TEXAS INSTRUMENTS" at 64.052,-74.727 h1.52
M6 Assembly Bottom:
  lines w0.254: -73.247,-66.167 94.443,-66.167 ; -73.197,-71.332 94.443,-71.332 ; -37.484,-76.661 -37.484,-71.509 ; -21.685,-66.167 -21.685,-61.002 ; -0.349,-66.167 -0.349,-61.002 ; 31.832,-76.496 31.832,-61.002 ; 54.413,-76.496 94.431,-76.496 94.431,-61.002 -73.247,-61.002 -73.247,-76.496 -7.284,-76.496 94.443,-76.496 94.443,-61.002
  text "COMPONENTS MARKED 'DNP' SHOULD NOT BE POPULATED." at 89.173,-55.77 h1.52
  text ".VariantName" at 62.655,-58.716 h1.52
  text "ASSEMBLY VARIANT:" at 89.046,-58.716 h1.52
  text ".VersionControl_RevNumber" at -39.516,-64.359 h1.52
  text "SVN REV:" at -26.664,-64.359 h1.52
  text ".PCB_Rev" at -12.783,-64.359 h1.52
  text "REV:" at -5.379,-64.359 h1.52
  text ".PRJ_Number" at 16.072,-64.359 h1.52
  text "BOARD #:" at 29.927,-64.359 h1.52
  text "PCB VIEWED FROM BOTTOM SIDE" at 92.83,-64.359 h1.52
  text ".TID" at 16.072,-69.524 h1.52
  text "TID #:" at 29.927,-69.524 h1.52
  text "TEXAS INSTRUMENTS" at -42.844,-74.739 h1.52
  text ".Print_Time" at -10.725,-74.739 h1.52
  text ".Print_Date" at 7.791,-74.739 h1.52
  text "GENERATED    :" at 29.877,-74.739 h1.52
  text ".plot_File_Name" at 72.371,-74.739 h1.52
  text "PLOT NAME =" at 92.83,-74.739 h1.52
M9 Title Sheet:
  drawing of 57 lines, arcs and shapes, not listed
  text "1" at -47.026,156.435 h1.78
  text "2" at 16.364,156.435 h1.78
  text "3" at 79.593,156.435 h1.78
  text "4" at 143.262,156.435 h1.78
  text "5" at 206.737,156.435 h1.78
  text "6" at 270.364,156.435 h1.78
  text "A" at -76.397,127.402 h1.78
  text "A" at 299.523,127.402 h1.78
  text "B" at -76.397,66.95 h1.78
  text "B" at 299.523,66.95 h1.78
  text "C" at -76.397,6.625 h1.78
  text "C" at 299.523,6.625 h1.78
  text "PROJECT TITLE:" at 222.307,-40.644 h1.14
  text ".PRJ_Title" at 223.577,-44.031 h1.78
  text "DESIGNED FOR:" at 222.307,-48.289 h1.14
  text ".PRJ_Customer" at 223.577,-51.845 h1.78
  text "D" at -76.397,-53.573 h1.78
  text "D" at 299.523,-53.573 h1.78
  text "FILE NAME:" at 222.307,-55.909 h1.14
  text ".PCB_File_Name_No_Path" at 223.577,-58.957 h1.78
  text "Texas Instruments (TI) and/or its licensors do not warrant the accuracy or completeness of this specification" at 96.082,-63.068 h1.14
  text "ENGINEER:" at 222.307,-63.275 h1.14
  text "LAYOUT BY:" at 260.534,-63.275 h1.14
  text "or any information contained therein. TI and/or its licensors do not warrant that this design will meet" at 94.939,-65.93 h1.14
  text ".PRJ_Engineer" at 223.577,-67.212 h1.78
  text ".PCB_Layout" at 261.817,-67.212 h1.78
  text "the specifications, will be suitable for your application or fit for any particular purpose, or will operate in" at 94.939,-68.792 h1.14
  text ".Layer_Name" at -51.162,-69.498 h1.52
  text "ALTIUM DESIGNER VERSION:" at 260.534,-71.149 h1.14
  text "an implementation. TI and/or its licensors do not warrant that the design is production worthy. You should" at 94.939,-71.653 h1.14
  text "completely validate and test your design implementation to confirm the system functionality for your application." at 96.082,-74.515 h1.14
  text ".print_Scale" at 223.577,-74.536 h1.78
  text ".Application_BuildNumber" at 261.817,-74.536 h1.78
  text "1" at -47.026,-79.785 h1.78
  text "2" at 16.364,-79.785 h1.78
  text "3" at 79.593,-79.785 h1.78
  text "4" at 143.262,-79.785 h1.78
  text "5" at 206.737,-79.785 h1.78
  text "6" at 270.364,-79.785 h1.78
M10 Fab Notes:
  drawing of 189 lines, arcs and shapes, not listed
  text "DESIGN INFORMATION" at 248.685,113.754 h1.52
  text "MIN. TRACK WIDTH:" at 232.313,110.398 h1.52
  text "8" at 260.158,110.398 h1.52
  text "MIL" at 264.089,110.398 h1.52
  text "MIN. CLEARANCE:" at 232.313,107.245 h1.52
  text "0.2" at 258.634,107.246 h1.52
  text "mm" at 264.089,107.245 h1.52
  text "MIN. VIA PAD SIZE:" at 232.313,104.093 h1.52
  text "24" at 259.396,104.093 h1.52
  text "MIL" at 264.089,104.093 h1.52
  text "0.05mm (2MIL)" at 249.966,100.793 h1.52
  text "MINIMUM ANNULAR RING" at 223.951,100.584 h1.52
  text "EXTERNAL" at 267.95,100.584 h1.52
  text "PER" at 229.031,97.787 h1.52
  text "IPC-D-275 CLASS 2 LEVEL C" at 234.619,97.787 h1.52
  text "MIL, HOLES" at 272.42,95.235 h1.52
  text "+/-" at 262.452,95.017 h1.52
  text "+/-" at 284.143,95.017 h1.52
  text "REGISTRATION TOLERANCES:" at 223.951,94.99 h1.52
  text "METAL" at 254.425,94.99 h1.52
  text "5" at 269.061,94.99 h1.52
  text "3" at 290.219,94.99 h1.52
  text "MIL" at 293.172,94.99 h1.52
  text "HOLE SIZE TOLERANCE (UNLESS OTHERWISE SPECIFIED):" at 223.951,92.493 h1.52
  text "+/-" at 284.143,92.42 h1.52
  text "3" at 290.219,92.393 h1.52
  text "MIL" at 293.172,92.393 h1.52
  text "MATERIAL:" at 222.052,88.896 h1.52
  text "FR-4 High Tg" at 247.108,85.632 h1.52
  text "X" at 243.439,85.429 h1.52
  text "FR-408" at 232.745,85.314 h1.52
  text "OTHER" at 270.54,85.314 h1.52
  text "62 MIL (1.6mm) +/-10%" at 240.876,81.681 h1.52
  text "X" at 237.825,81.619 h1.52
  text "THICKNESS:" at 223.951,81.472 h1.52
  text "OTHER" at 273.512,81.472 h1.52
  text "TOLERANCE:" at 223.951,77.959 h1.52
  text "X" at 245.496,77.959 h1.52
  text "ANSI IPC-6012 TYPE 3 CLASS 2" at 250.018,77.959 h1.52
  text "OTHER +/-" at 250.017,74.297 h1.52
  text "BOW & TWIST:" at 223.951,70.609 h1.52
  text "X" at 245.496,70.609 h1.52
  text "ANSI IPC-6012 TYPE 3 CLASS 2" at 250.018,70.609 h1.52
  text "OTHER +/-" at 250.017,66.883 h1.52
  text "DRILLING:" at 222.052,63.565 h1.52
  text "NC_DRILL FILES" at 266.781,60.893 h1.52
  text "REFERENCE:" at 223.951,60.793 h1.52
  text "X" at 240.645,60.791 h1.52
  text "AS SHOWN" at 245.166,60.793 h1.52
  text "X" at 263.53,60.793 h1.52
  text "OTHER" at 274.35,57.18 h1.52
  text "PTH COPPER THICKNESS:" at 223.943,57.091 h1.52
  text "X" at 252.879,57.091 h1.52
  text "20-30 um" at 256.13,57.091 h1.52
  text "BOARD FINISH:" at 222.052,53.342 h1.52
  text "SILKSCREEN:" at 225.995,50.544 h1.52
  text "X" at 250.322,50.544 h1.52
  text "TOP" at 253.294,50.544 h1.52
  text "X" at 263.276,50.544 h1.52
  text "BOTTOM" at 266.273,50.544 h1.52
  text "SILKSCREEN COLOR:" at 225.995,46.603 h1.52
  text "X" at 250.297,46.603 h1.52
  text "WHITE" at 253.294,46.603 h1.52
  text "OTHER" at 266.273,46.603 h1.52
  text "X" at 253.624,42.959 h1.52
  text "GREEN" at 256.621,42.959 h1.52
  text "OTHER" at 272.318,42.959 h1.52
  text "SOLDER RESIST COLOR:" at 225.995,42.785 h1.52
  text "X" at 253.624,39.041 h1.52
  text "MATTE" at 256.621,39.041 h1.52
  text "SEMI-GLOSS" at 272.307,39.025 h1.52
  text "IMMERSION GOLD (ENIG)" at 249.001,34.653 h1.52
  text "ENEPIG" at 282.975,34.469 h1.52
  text "SURFACE FINISH:" at 222.052,34.444 h1.52
  text "X" at 244.48,34.444 h1.52
  text "IMM. TIN/SILVER OR EQUIV" at 230.422,30.956 h1.52
  text "OTHER" at 266.781,30.856 h1.52
  text "ARRAY/PANEL:" at 222.052,26.909 h1.52
  text "CUT AND TRIM PER M1 BOARD OUTLINE" at 249.001,26.701 h1.52
  text "N.C. ROUTE" at 249.001,23.247 h1.52
  text "X" at 266.477,23.247 h1.52
  text "V. SCORE" at 270.998,23.247 h1.52
  text "CERTIFICATION:" at 222.052,19.967 h1.52
  text "MATERIALS AND WORKMANSHIP FOR ALL PCBS" at 240.467,19.967 h1.52
  text "TO MEET OR EXCEED THE REQUIREMENTS OF:" at 240.467,17.578 h1.52
  text "X" at 231.26,14.311 h1.52
  text "ANSI IPC-A-600F CLASS ->" at 234.511,14.311 h1.52
  text "X" at 276.37,14.311 h1.52
  text "2" at 279.164,14.311 h1.52
  text "1" at 271.163,14.273 h1.52
  text "3" at 288.155,14.273 h1.52
  text "X" at 251.884,10.56 h1.52
  text "RoHS" at 255.135,10.56 h1.52
  text "OTHER" at 271.503,10.56 h1.52
  text "PER ORDER" at 281.589,10.56 h1.52
  text "ALL BOARDS MUST MEET OR EXCEED UL94-V0 REQUIREMENTS." at 222.751,6.652 h1.52
  text "PCB MUST BEAR THE UL94V-0 UL REGISTERED MATERIAL ID NUMBER" at 222.751,3.704 h1.52
  text "ADDITIONAL REQUIREMENTS:" at 222.052,-0.599 h1.52
  text "MICROSECTION:" at 223.951,-3.32 h1.52
  text "YES" at 246.957,-3.32 h1.52
  text "REQUIRED" at 268.839,-6.986 h1.52
  text "BARE BOARD ELEC. TEST:" at 223.951,-7.059 h1.52
  text "NONE" at 257.117,-7.059 h1.52
  text "X" at 265.842,-7.059 h1.52
  text "PER ORDER" at 283.875,-7.059 h1.52
  text "XX MIL VIAS REQUIRE NON-CONDUCTIVE FILL AND PLANARIZE" at 228.222,-12.264 h1.5
  text "XX MIL VIAS REQUIRE CONDUCTIVE FILL AND PLANARIZE" at 228.425,-14.905 h1.52
  text "OUTER XX MIL TRACES REQUIRE 50 OHM SINGLE-ENDED IMPEDANCE" at 228.4,-19.055 h1.47
  text "LAYER 2 & 3 (INNER LAYERS) XX MIL WIDE, XX MIL SPACE / TRACES REQUIRE 100 OHM DIFFERENTIAL IMPEDANCE" at 228.197,-25.042 h1.52
  text ".Layer_Name" at -51.162,-69.498 h1.52
M11 Gerber Information:
  lines w0.254: -73.235,-71.319 94.405,-71.319 ; -73.235,-66.154 94.456,-66.154 ; -73.235,-60.989 -73.235,-76.483 28.492,-76.483 94.456,-76.483 94.456,-60.99 -73.222,-60.99 -73.222,-76.483 -33.204,-76.483 ; -10.624,-76.483 -10.624,-60.99 ; 21.558,-66.154 21.558,-60.99 ; 42.894,-66.154 42.894,-60.99 ; 58.693,-76.649 58.693,-71.497
  text "ALL ARTWORK VIEWED FROM TOP SIDE" at -71.622,-64.347 h1.52
  text "BOARD #:" at -8.719,-64.347 h1.52
  text ".PRJ_Number" at 5.137,-64.347 h1.52
  text "REV:" at 26.587,-64.347 h1.52
  text ".PCB_Rev" at 33.991,-64.347 h1.52
  text "SVN REV:" at 47.872,-64.347 h1.52
  text ".VersionControl_RevNumber" at 60.725,-64.347 h1.52
  text "LAYER NAME =" at -71.622,-69.498 h1.52
  text "TID #:" at -8.719,-69.511 h1.52
  text ".TID" at 5.137,-69.511 h1.52
  text "PLOT NAME =" at -71.622,-74.727 h1.52
  text ".plot_File_Name" at -51.162,-74.727 h1.52
  text "GENERATED    :" at -8.668,-74.727 h1.52
  text ".Print_Date" at 13.417,-74.727 h1.52
  text ".Print_Time" at 31.934,-74.727 h1.52
  text "TEXAS INSTRUMENTS" at 64.052,-74.727 h1.52
M12 Stackup:
  drawing of 354 lines, arcs and shapes, not listed
  text "Layer" at 182.552,144.23 h1.52
  text "Name" at 192.964,144.23 h1.52
  text "Material" at 216.579,144.23 h1.52
  text "Thickness" at 238.417,144.23 h1.52
  text "Constant" at 254.923,144.23 h1.52
  text "Board Layer Stack" at 269.398,144.23 h1.52
  text "Board Layer Stack" at 297.838,144.23 h1.52
  text "Board Layer Stack" at 326.277,144.23 h1.52
  text "1" at 182.552,141.182 h1.52
  text "Top Overlay" at 192.964,141.182 h1.52
  text "2" at 182.552,138.134 h1.52
  text "Top Solder" at 192.964,138.134 h1.52
  text "Solder Resist" at 216.579,138.134 h1.52
  text "0.40mil" at 238.417,138.134 h1.52
  text "3.5" at 254.923,138.134 h1.52
  text "3" at 182.552,135.086 h1.52
  text "Top Layer" at 192.964,135.086 h1.52
  text "Copper" at 216.579,135.086 h1.52
  text "1.40mil" at 238.417,135.086 h1.52
  text "4" at 182.552,132.038 h1.52
  text "Dielectric1" at 192.964,132.038 h1.52
  text "FR-4" at 216.579,132.038 h1.52
  text "59.20mil" at 238.417,132.038 h1.52
  text "4.8" at 254.923,132.038 h1.52
  text "5" at 182.552,128.99 h1.52
  text "Bottom Layer" at 192.964,128.99 h1.52
  text "Copper" at 216.579,128.99 h1.52
  text "1.40mil" at 238.417,128.99 h1.52
  text "6" at 182.552,125.942 h1.52
  text "Bottom Solder" at 192.964,125.942 h1.52
  text "Solder Resist" at 216.579,125.942 h1.52
  text "0.40mil" at 238.417,125.942 h1.52
  text "3.5" at 254.923,125.942 h1.52
  text "7" at 182.552,122.894 h1.52
  text "Bottom Overlay" at 192.964,122.894 h1.52
  text ".Layer_Name" at -51.162,-69.498 h1.52
M13 Component Bodies Top:
  text ".Layer_Name" at -51.162,-69.498 h1.52
M14 Component Bodies Bottom:
  text ".Layer_Name" at -51.162,-69.498 h1.52
M15 Courtyards Top:
  text ".Layer_Name" at -51.162,-69.498 h1.52
M16 Courtyards Bottom:
  text ".Layer_Name" at -51.162,-69.498 h1.52
Drill Drawing:
  circle w0.254: c70.42,41.832 r0.702
  lines w0.254: 69.719,34.815 71.122,34.815 71.122,36.219 69.719,36.219 69.719,34.815 ; 69.719,38.324 70.07,38.324 70.42,37.973 70.771,38.324 71.122,38.324 70.771,38.675 71.122,39.026 70.771,39.026 70.42,39.376 70.07,39.026 69.719,39.026 70.07,38.675 69.719,38.324 ; 69.719,44.288 70.42,44.639 71.122,44.288 70.771,44.99 71.122,45.692 70.42,45.341 69.719,45.692 70.07,44.99 69.719,44.288
  lines w0.305: 68.446,33.868 150.526,33.868 ; 68.446,46.499 150.526,46.499 ; 77.028,30.71 77.028,49.657 ; 85.461,30.71 85.461,49.657 ; 101.63,30.71 101.63,49.657 ; 108.212,30.71 108.212,49.657 ; 117.741,30.71 117.741,49.657 ; 136.139,30.71 136.139,49.657 ; 68.446,30.71 150.526,30.71 150.526,49.657 68.446,49.657 68.446,30.71
  text "Symbol" at 70.341,47.446 h1.83
  text "Quantity" at 77.975,47.446 h1.83
  text "Finished Hole Size" at 86.408,47.446 h1.83
  text "Plated" at 102.577,47.446 h1.83
  text "Hole Type" at 109.159,47.446 h1.83
  text "Drill Layer Pair" at 118.688,47.446 h1.83
  text "Hole Tolerance" at 137.086,47.446 h1.83
  text "1" at 77.975,44.288 h1.52
  text "708.66mil (18.000mm)" at 86.408,44.288 h1.52
  text "NPTH" at 102.577,44.288 h1.52
  text "Round" at 109.159,44.288 h1.52
  text "Top Layer - Bottom Layer" at 118.688,44.288 h1.52
  text "42" at 77.975,41.131 h1.52
  text "12.00mil (0.305mm)" at 86.408,41.131 h1.52
  text "PTH" at 102.577,41.131 h1.52
  text "Round" at 109.159,41.131 h1.52
  text "Top Layer - Bottom Layer" at 118.688,41.131 h1.52
  text "6" at 77.975,37.973 h1.52
  text "29.53mil (0.750mm)" at 86.408,37.973 h1.52
  text "PTH" at 102.577,37.973 h1.52
  text "Round" at 109.159,37.973 h1.52
  text "Top Layer - Bottom Layer" at 118.688,37.973 h1.52
  text "24" at 77.975,34.815 h1.52
  text "31.50mil (0.800mm)" at 86.408,34.815 h1.52
  text "PTH" at 102.577,34.815 h1.52
  text "Round" at 109.159,34.815 h1.52
  text "Top Layer - Bottom Layer" at 118.688,34.815 h1.52
  text "73 Total" at 77.975,31.658 h1.52
  text ".Layer_Name" at -51.162,-69.498 h1.52
M17 Embedded Cavity:
  text ".Layer_Name" at -51.162,-69.498 h1.52
M18 Embedded Assembly:
  text ".Layer_Name" at -51.162,-69.498 h1.52
M19 Embedded Keepout:
  text ".Layer_Name" at -51.162,-69.498 h1.52
Alignment:
  lines w0.025: -25.35,0 -0.025,0 ; -1.317,-13.71 0.778,-10.71 ; -1.317,-10.71 0.778,-13.71 ; 0,-25.325 0,0 ; 0,25.325 0,0 ; 25.325,0 0,0 ; -13.486,-0.836 -12.425,0.225 ; -13.486,-0.836 -14.546,0.225 -13.486,1.286 ; -13.486,-0.836 -12.425,-1.896 -11.364,-0.836 ; -13.486,1.286 -12.425,0.225 ; -13.486,1.286 -12.425,2.346 -11.364,1.286 ; -12.425,0.225 -11.364,1.286 ; -12.425,0.225 -11.364,-0.836 ; -11.364,-0.836 -10.304,0.225 -11.364,1.286 ; -1.77,-12.21 -1.77,-10.71 -0.27,-10.71 ; -1.77,-12.21 -0.27,-12.21 ; -1.77,-12.21 -1.77,-13.71 -0.27,-13.71 ; -0.27,-13.71 1.23,-13.71 1.23,-12.21 ; -0.27,-13.71 -0.27,-12.21 ; -0.27,-12.21 1.23,-12.21 ; -0.27,-12.21 -0.27,-10.71 ; -0.27,-10.71 1.23,-10.71 1.23,-12.21

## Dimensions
-9,0 to 8.975,0 on M2 Board Dimensions
-65.818,-57.853 to -40.418,-57.853 on M2 Board Dimensions
-12.75,25.4 to -14.5,-25.425 on M2 Board Dimensions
